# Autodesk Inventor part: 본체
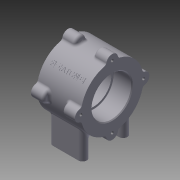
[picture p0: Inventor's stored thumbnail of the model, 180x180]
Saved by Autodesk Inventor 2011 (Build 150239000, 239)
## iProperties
Created: 2015-03
Part Number: 본체
Document SubType Name: Modeling
Designer: Administrator
Density: 2.71 g/cm^3
Material: 알루미늄-6061
Mass: 451.257 g
Surface Area: 331.783 cm^2
Volume: 166.515 cm^3
Author: Administrator
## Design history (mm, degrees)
sketch "스케치1"
  geometry: L1 (-26, 0)-(26, 0); L2 (-26, 0)-(-26, 37); L3 (26, 37)-(26, 0); L4 (26, 37)-(-26, 37); 2 further points
  constraints: 8 end point, 1 coincident, 1 midpoint
  dimensions: "d0" = 52 distance of L1.start L1.end; "d1" = 37 distance of L1.start L2.end
revolve "회전1" sketch "스케치1" stored, may be unused: angle "d2" = 90 deg
sketch "스케치2"
  geometry: L1 (0, 0)-(0, -56) reference; L2 (-29, -56)-(-29, 0); L3 (29, -56)-(29, 0); L4 (-29, -56)-(-19, -56); L5 (-19, -56)-(-19, 0.23); L6 (-19, 0.23)-(-29, 0); L7 (29, -56)-(19, -56); L8 (19, -56)-(19, -0.46); L9 (19, -0.46)-(29, 0); 1 further point
  constraints: 18 end point, 1 vertical, 1 vertical alignment
  dimensions: "d3" = 58 distance of L2.start L3.start; "d4" = 10 distance between parallel lines of L5 L2; "d5" = 10 distance between parallel lines of L3 L8; "d6" = 56 distance of L2.start L2.end; "d48" = 29 distance between parallel lines of L1 L2
extrude "돌출1" join sketch "스케치2" stored distance "d7" = 40; taper "d8" = 0 deg
sketch "스케치3"
  geometry: C1 r 7 at (0, 37); 1 further point
  constraints: 1 centre point, 1 vertical alignment, 1 other
extrude "돌출2" join sketch "스케치3" distance "d9" = 15; taper "d10" = 0 deg
fillet "모깎기1" dims "d11" = 3
sketch "스케치4"
  geometry: C1 r 23.5 at (0, -37); A1 r 37 centre (0, -37) between (9.104, -72.863) and (35.863, -46.104) reference
  constraints: 1 centre point, 1 coincident
  dimensions: "d15" = 47 diameter of C1
extrude "돌출3" cut sketch "스케치4" distance "d16" = 22; taper "d17" = 0 deg
sketch "스케치5"
  geometry: C1 r 23.5 at (-37, 0); A1 r 37 centre (-37, 0) between (-72.862, -9.104) and (-46.104, -35.863) reference
  constraints: 1 centre point, 1 coincident
extrude "돌출4" cut sketch "스케치5" distance "d18" = 22; taper "d19" = 0 deg
sketch "스케치6"
  geometry: C1 r 23.5 at (0, 0) reference; C2 r 21 at (0, 0)
  constraints: 1 centre point, 1 coincident
  dimensions: "d20" = 42 diameter of C2
extrude "돌출5" cut sketch "스케치6" stored distance "d21" = 22; taper "d22" = 0 deg
sketch "스케치7"
  geometry: A1 r 7 centre (0, 0) between (6.889, 1.239) and (-6.889, 1.239) reference; A2 r 7 centre (-37, -37) between (-38.239, -30.111) and (-38.239, -43.889) reference; A3 r 7 centre (0, -74) between (-6.889, -75.239) and (6.889, -75.239) reference; A4 r 7 centre (37, -37) between (38.239, -43.889) and (38.239, -30.111) reference
hole "Hole1" sketch "스케치7" at (-37, -37), (0, 0), (0, -74), (37, -37) diameter "d23" = 3.242; stored, may be unused: countersink angle "d27" = 90 deg, drill point angle "d29" = 118 deg; dims "d24" = 8, "d25" = 4, "d26" = 2, "d28" = 11
fillet "모깎기3" dims "d31" = 5
fillet "모깎기4" dims "d32" = 3, "d46" = 0.3
sketch "스케치8"
  geometry: A1 r 5 centre (30, -5) between (30, -10) and (30, 0) reference; A2 r 5 centre (0, -5) between (0, 0) and (0, -10) reference; 1 further point
hole "Hole2" sketch "스케치8" at (0, -5), (30, -5) diameter "d33" = 3.242; stored, may be unused: countersink angle "d37" = 90 deg, drill point angle "d39" = 118 deg; dims "d34" = 6, "d35" = 4, "d36" = 2, "d38" = 8
sketch "스케치9"
  geometry: L1 (0, 0)-(-26.163, 26.163); L2 (0, 0)-(-47.055, 0) reference; 2 further points
  constraints: 4 end point, 1 coincident, 1 horizontal
  dimensions: "d40" = 45 deg angle of L1 L2
node "작업 평면2"
sketch "스케치10"
  geometry: 2 further points
  constraints: 2 coincident, 1 other
feature "엠보싱1" sketch "스케치10" dims "d0" = 52, "d1" = 37, "d9" = 15, "d10" = 0, "d41" = 0.5, "d42" = 0
chamfer "모따기1" distance "d43" = 1; stored, may be unused: second distance "d44" = 2, angle "d45" = 45 deg
node "솔리드1"
pattern_circular "원형 패턴1" dims angle "d13" = 360 deg
mirror "대칭1"
mirror "대칭2"
mirror "대칭3"
